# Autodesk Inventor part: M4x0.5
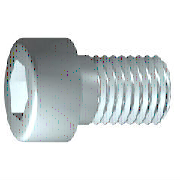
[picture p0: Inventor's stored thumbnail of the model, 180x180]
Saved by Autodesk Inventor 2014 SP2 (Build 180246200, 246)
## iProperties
IsCustomPart: 1
Company: 한국ATC센터
Created: 2014-10
Part Number: M4x0.5
Material: 강, 연강
Description: 6각머리 태핑 나사
Document SubType Name: Modeling
Standard: KS B 1003
Designer: 한국ATC센터
Standards Organization: KS
Language: ko-KR
Size Designation: M 4 x 16
Categories: <MemberInstance><Categories><Category DisplayName="조임쇠" InternalName="e4da775c-781d-43d5-af7c-5136215cf5a6" Mnemonic="FSTN"><Category DisplayName="볼트" InternalN
Density: 7.86 g/cm^3
Mass: 2.62973 g
Surface Area: 3.81119 cm^2
Volume: 0.334572 cm^3
Appearance: 강철
Author: KYOUNG IL JANG
Revision Number: 1
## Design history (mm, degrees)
sketch "스케치1"
  geometry: L1 (-1, 0)-(16, 0); L2 (16, 0)-(16, 2); L3 (16, 2)-(1.75, 2); L4 (1.75, 2)-(1.32, 2); L5 (1.32, 2)-(0, 2); L6 (0, 2)-(0, 3.5); L7 (0, 3.5)-(-4, 3.5); L8 (-4, 3.5)-(-4, 1.732); L9 (-4, 1.732)-(-2, 1.732); L10 (-2, 1.732)-(-1, 0); L11 (-8, 0)-(20, 0) reference; L12 (0, -0.7)-(0, 4.2) reference; L13 (1.75, 2)-(0, 2)
  constraints: 22 end point, 6 parallel, 2 collinear, 2 perpendicular, 1 horizontal, 1 point on line
  dimensions: "d1" = 14.25 distance from line of L3.end L2 (= GEL); "d2" = 0.42952 distance of L4.end L3.end (computed from GAL); "d3" = 4 distance between parallel lines of L8 L6 (= KOH); "d4" = 2 distance of L8.end L9.end (= INTI); "d5" = 60 deg angle of L10 L1; "d6" = 4 diameter of L3 L1 (= GD); "d7" = 4 diameter of L5 L1 (= BDM); "d8" = 3.4641 diameter of L9 L1 (= 1.1547 x SW); "d9" = 7 diameter of L7 L1 (= KOD); "d26" = 16 distance between parallel lines of L12 L2 (= NLG)
revolve "본체" sketch "스케치1" stored, may be unused: angle "d10" = 90 deg
sketch "스케치2"
  geometry: L1 (0, -4.9)-(0, 4.9) reference; L2 (-4.9, 0)-(4.9, 0) reference; L3 (1.732, 0)-(0.866, -1.5); L4 (0.866, -1.5)-(-0.866, -1.5); L5 (-0.866, -1.5)-(-1.732, 0); L6 (-1.732, 0)-(-0.866, 1.5); L7 (-0.866, 1.5)-(0.866, 1.5); L8 (0.866, 1.5)-(1.732, 0); 2 further points
  constraints: 12 end point, 1 coincident, 1 horizontal alignment, 1 point on line, 12 other
extrude "슬롯" join sketch "스케치2" stored distance "d11" = 10; taper "d12" = 0 deg
workplane "Work Plane1"
fillet "Fillet2" dims "d30" = 0.1 (= R)
body "Solid1"
fillet "모깎기1" dims "d17" = 0.4 (= RR)
feature "스레드" dims "d13" = 14.25 (= GEL), "d14" = 0
chamfer "모따기1" distance "d15" = 0.42941 (= -0.5 x SPD + 0.5 x GD); stored, may be unused: second distance "d16" = 0.42941 (= GUL), angle "d27" = 45 deg
other parameters: "GD" = 4 (= NND) [user parameter; used in 2 equation terms], "NLG" = 16 [user parameter; used in 1 equation term], "GEL" = 14.25 [user parameter; used in 2 equation terms], "KOD" = 7 [user parameter; used in 1 equation term], "KOH" = 4 [user parameter; used in 1 equation term], "INTI" = 2 [user parameter; used in 1 equation term], "GAL" = 0.42941 (= 0.61345 x PTC) [user parameter; used in 1 equation term], "GUL" = 0.42941 (= 0.61345 x PTC) [user parameter; used in 1 equation term], "BDM" = 4 (= NND) [user parameter; used in 1 equation term], "SW" = 3 [user parameter; used in 2 equation terms], "RR" = 0.4 [user parameter; used in 1 equation term], "SPD" = 3.14117 (= NND - 1.2269 x PTC) [user parameter; used in 1 equation term], "d19" = 0, "d28" = 0, "d29" = 0, "R" = 0.1 [user parameter; used in 1 equation term], "PHH" = 0.2 [user parameter], "GD1" = 3.14117 (= THREADDIA - 1.2269 x PTC) [user parameter], "THREADDIA" = 4 [user parameter; used in 1 equation term], "FAWI" = 45 deg [user parameter], "TPU" = 14.28571 (computed from PTC) [user parameter], "PTC" = 0.7 [user parameter; used in 5 equation terms], "NND" = 4 [user parameter; used in 3 equation terms], "TOA" = 30 deg [user parameter], "E0" = 3.465 (= 1.155 x SW) [user parameter]
